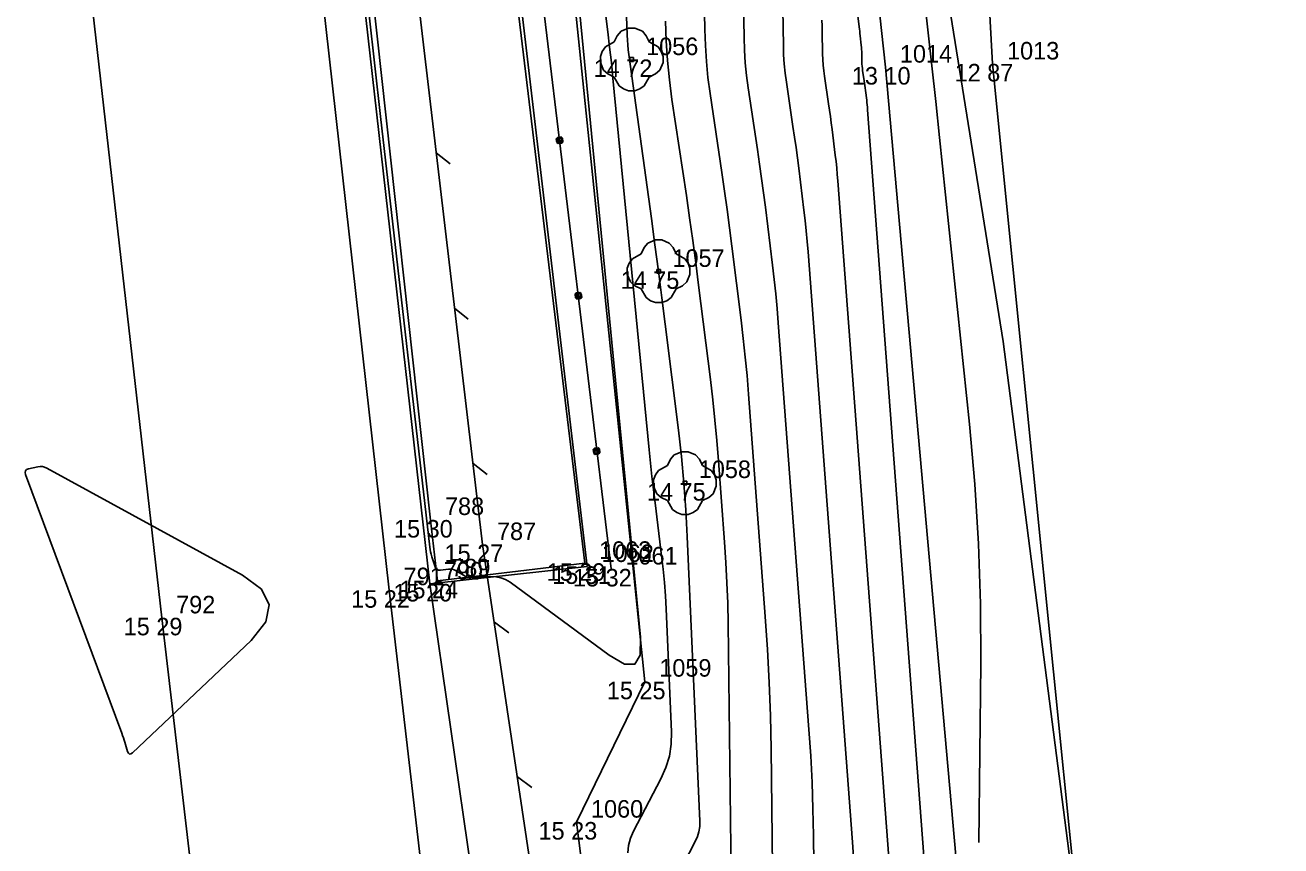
# Model space of a CAD drawing. Extents: x -711234 to -710007, y -1026313 to -1025448.
# Drawn here: x -710920.63 to -710900.59, y -1025784.48 to -1025771.38 of the extents above; entities that cross this region are included whole.
import ezdxf

# ---------------------------------------------------------------- set-up
doc = ezdxf.new("R2010")
doc.units = 0
for name, color, linetype in [('Ex_Major Contours', 7, 'Continuous'), ('Ex_Minor Contours', 7, 'Continuous'), ('Z_body', 7, 'Continuous'), ('Z_body_cisla', 7, 'Continuous'), ('Z_body_vysky_redukovane', 7, 'Continuous'), ('Z_chodnik', 7, 'Continuous'), ('Z_hrany_paty', 7, 'Continuous'), ('Z_katastr_hranice', 7, 'Continuous'), ('Z_komunikace', 7, 'Continuous'), ('Z_obruba', 7, 'Continuous'), ('Z_pole_rozhranni', 7, 'Continuous'), ('Z_svodidla', 7, 'Continuous'), ('Z_svodidla_znacky', 7, 'Continuous'), ('Z_vdz12_plna', 7, 'Continuous'), ('Z_vdz25_plna', 7, 'Continuous'), ('Z_zabradli', 7, 'Continuous'), ('Z_zabradli_znaky', 7, 'Continuous'), ('Z_zelen_jednotliva', 7, 'Continuous')]:
    doc.layers.add(name, color=color, linetype=linetype)

# ---------------------------------------------------------------- blocks, each defined once
blk = doc.blocks.new('POINT_DISPLAY')
blk.add_line((0, 0), (0, 0))
blk = doc.blocks.new('Z24')
for p, q in [((-0.23, 0.38), (-0.17, 0.45)), ((-0.17, 0.45), (-0.05, 0.5)), ((-0.05, 0.5), (0.05, 0.5)), ((0.05, 0.5), (0.17, 0.45)), ((0.17, 0.45), (0.23, 0.38)), ((-0.42, 0.2), (-0.28, 0.28)), ((-0.28, 0.28), (-0.23, 0.38)), ((0.23, 0.38), (0.28, 0.28)), ((0.28, 0.28), (0.42, 0.2)), ((-0.5, 0.05), (-0.47, 0.13)), ((-0.5, -0.05), (-0.5, 0.05)), ((-0.47, 0.13), (-0.42, 0.2)), ((-0.03, -0.03), (-0.03, 0.03)), ((-0.03, 0.03), (0.03, 0.03)), ((0.03, 0.03), (0.03, -0.03)), ((0.42, 0.2), (0.47, 0.13)), ((0.47, 0.13), (0.5, 0.05)), ((0.5, 0.05), (0.5, -0.05)), ((-0.45, -0.17), (-0.5, -0.05)), ((-0.38, -0.23), (-0.45, -0.17)), ((0.03, -0.03), (-0.03, -0.03)), ((0.45, -0.17), (0.38, -0.23)), ((0.5, -0.05), (0.45, -0.17)), ((-0.28, -0.28), (-0.38, -0.23)), ((-0.2, -0.42), (-0.28, -0.28)), ((0.28, -0.28), (0.2, -0.42)), ((0.38, -0.23), (0.28, -0.28)), ((-0.13, -0.47), (-0.2, -0.42)), ((-0.05, -0.5), (-0.13, -0.47)), ((0.05, -0.5), (-0.05, -0.5)), ((0.13, -0.47), (0.05, -0.5)), ((0.2, -0.42), (0.13, -0.47))]:
    blk.add_line(p, q)
blk = doc.blocks.new('Z529')
blk.add_line((0, 0), (0.2, 0.2))
blk = doc.blocks.new('Z530')
for p, q in [((-0.05, 0.03), (-0.03, 0.05)), ((-0.05, -0.03), (-0.05, 0.03)), ((-0.03, 0.05), (0.03, 0.05)), ((-0.03, -0.03), (-0.03, 0.03)), ((-0.03, 0.03), (0.03, 0.03)), ((-0.03, -0.03), (0.03, 0.03)), ((0.03, 0.05), (0.05, 0.03)), ((0.03, 0.03), (0.03, -0.03)), ((0.05, 0.03), (0.05, -0.03)), ((-0.03, -0.05), (-0.05, -0.03)), ((0.03, -0.03), (-0.03, -0.03)), ((0.03, -0.05), (-0.03, -0.05)), ((0.05, -0.03), (0.03, -0.05))]:
    blk.add_line(p, q)

msp = doc.modelspace()

# ---------------------------------------------------------------- linework, layer by layer
at = {"layer": 'Ex_Major Contours'}
for points in [[(-710905.412, -1025784.425), (-710905.38, -1025781.577), (-710905.384, -1025780.619), (-710905.414, -1025779.662), (-710905.473, -1025778.706), (-710905.558, -1025777.751), (-710906.037, -1025773.174), (-710906.098, -1025772.601), (-710906.16, -1025772.029), (-710906.224, -1025771.456), (-710906.29, -1025770.884), (-710906.667, -1025767.642), (-710906.688, -1025767.556), (-710906.729, -1025767.487), (-710906.791, -1025767.436), (-710906.872, -1025767.402), (-710907.239, -1025767.301), (-710907.321, -1025767.267), (-710907.384, -1025767.216), (-710907.428, -1025767.147), (-710907.452, -1025767.062), (-710909.105, -1025756.206)], [(-710909.171, -1025770.773), (-710909.157, -1025771.58), (-710909.15, -1025771.781), (-710909.137, -1025771.982), (-710909.117, -1025772.183), (-710909.09, -1025772.382), (-710908.943, -1025773.369), (-710908.91, -1025773.599), (-710908.877, -1025773.829), (-710908.847, -1025774.059), (-710908.817, -1025774.289), (-710908.703, -1025775.211), (-710908.675, -1025775.442), (-710908.651, -1025775.672), (-710908.629, -1025775.904), (-710908.611, -1025776.135), (-710908.122, -1025782.622), (-710908.094, -1025783.045), (-710908.072, -1025783.468), (-710908.057, -1025783.891), (-710908.049, -1025784.315), (-710908.022, -1025786.591)], [(-710911.01, -1025784.594), (-710910.999, -1025784.474), (-710910.969, -1025784.357), (-710910.92, -1025784.244), (-710910.483, -1025783.411), (-710910.403, -1025783.232), (-710910.349, -1025783.048), (-710910.319, -1025782.858), (-710910.315, -1025782.662), (-710910.401, -1025780.7), (-710910.413, -1025780.488), (-710910.428, -1025780.276), (-710910.448, -1025780.064), (-710910.472, -1025779.853), (-710910.578, -1025779.008), (-710910.603, -1025778.796), (-710910.627, -1025778.585), (-710910.65, -1025778.373), (-710910.671, -1025778.161), (-710911.249, -1025772.228), (-710911.274, -1025771.98), (-710911.302, -1025771.733), (-710911.332, -1025771.487), (-710911.365, -1025771.24)]]:
    msp.add_lwpolyline(points, dxfattribs=at)
at = {"layer": 'Ex_Minor Contours'}
for points in [[(-710915.142, -1025771.224), (-710915.051, -1025772.031), (-710914.959, -1025772.838), (-710914.174, -1025779.712), (-710914.168, -1025779.751), (-710914.161, -1025779.789), (-710914.152, -1025779.827), (-710914.141, -1025779.865), (-710914.088, -1025780.026), (-710914.076, -1025780.053), (-710914.057, -1025780.071), (-710914.033, -1025780.08), (-710914.004, -1025780.08), (-710913.875, -1025780.065), (-710913.843, -1025780.063), (-710913.812, -1025780.067), (-710913.783, -1025780.076), (-710913.754, -1025780.09), (-710913.608, -1025780.177), (-710913.598, -1025780.185), (-710913.595, -1025780.191), (-710913.6, -1025780.196), (-710913.612, -1025780.2), (-710913.676, -1025780.211), (-710913.688, -1025780.214), (-710913.692, -1025780.215), (-710913.688, -1025780.216), (-710913.676, -1025780.215), (-710913.199, -1025780.184), (-710913.116, -1025780.185), (-710913.037, -1025780.201), (-710912.963, -1025780.23), (-710912.892, -1025780.274), (-710911.312, -1025781.438), (-710911.066, -1025781.579), (-710910.9, -1025781.578), (-710910.815, -1025781.436), (-710910.809, -1025781.152), (-710912.067, -1025768.238)], [(-710909.802, -1025770.418), (-710909.784, -1025771.449), (-710909.775, -1025771.707), (-710909.758, -1025771.963), (-710909.733, -1025772.219), (-710909.699, -1025772.475), (-710909.511, -1025773.735), (-710909.468, -1025774.029), (-710909.427, -1025774.323), (-710909.387, -1025774.617), (-710909.35, -1025774.911), (-710909.203, -1025776.089), (-710909.169, -1025776.384), (-710909.137, -1025776.679), (-710909.11, -1025776.974), (-710909.086, -1025777.27), (-710908.819, -1025780.82), (-710908.783, -1025781.348), (-710908.756, -1025781.875), (-710908.737, -1025782.404), (-710908.727, -1025782.932), (-710908.693, -1025785.772)], [(-710908.54, -1025771.128), (-710908.53, -1025771.71), (-710908.525, -1025771.856), (-710908.516, -1025772.001), (-710908.501, -1025772.146), (-710908.482, -1025772.29), (-710908.376, -1025773.002), (-710908.351, -1025773.168), (-710908.328, -1025773.335), (-710908.306, -1025773.501), (-710908.285, -1025773.667), (-710908.202, -1025774.333), (-710908.182, -1025774.499), (-710908.165, -1025774.666), (-710908.149, -1025774.833), (-710908.135, -1025775), (-710907.426, -1025784.423), (-710907.405, -1025784.741)], [(-710911.034, -1025771.236), (-710911.022, -1025771.544), (-710911.018, -1025771.621), (-710911.012, -1025771.697), (-710911.005, -1025771.774), (-710910.995, -1025771.85), (-710910.636, -1025774.466), (-710910.579, -1025774.888), (-710910.523, -1025775.31), (-710910.468, -1025775.733), (-710910.415, -1025776.155), (-710910.205, -1025777.845), (-710910.157, -1025778.268), (-710910.117, -1025778.691), (-710910.086, -1025779.116), (-710910.063, -1025779.541), (-710909.863, -1025784.087), (-710909.865, -1025784.172), (-710909.878, -1025784.254), (-710909.901, -1025784.333), (-710909.936, -1025784.411), (-710910.124, -1025784.77)], [(-710909.364, -1025784.954), (-710909.412, -1025780.934), (-710909.418, -1025780.608), (-710909.43, -1025780.283), (-710909.447, -1025779.958), (-710909.468, -1025779.633), (-710909.566, -1025778.334), (-710909.593, -1025778.009), (-710909.623, -1025777.685), (-710909.657, -1025777.361), (-710909.695, -1025777.037), (-710909.882, -1025775.533), (-710909.928, -1025775.175), (-710909.976, -1025774.817), (-710910.026, -1025774.459), (-710910.078, -1025774.101), (-710910.307, -1025772.567), (-710910.349, -1025772.256), (-710910.38, -1025771.945), (-710910.4, -1025771.632), (-710910.411, -1025771.319)], [(-710906.73, -1025786.225), (-710907.66, -1025773.866), (-710907.669, -1025773.763), (-710907.678, -1025773.66), (-710907.689, -1025773.557), (-710907.701, -1025773.455), (-710907.752, -1025773.045), (-710907.765, -1025772.943), (-710907.779, -1025772.84), (-710907.793, -1025772.738), (-710907.808, -1025772.636), (-710907.874, -1025772.198), (-710907.885, -1025772.109), (-710907.894, -1025772.02), (-710907.9, -1025771.931), (-710907.903, -1025771.841), (-710907.91, -1025771.482), (-710907.912, -1025771.393), (-710907.917, -1025771.303)], [(-710907.34, -1025771.235), (-710907.32, -1025771.408), (-710907.316, -1025771.444), (-710907.312, -1025771.48), (-710907.307, -1025771.516), (-710907.304, -1025771.552), (-710907.287, -1025771.703), (-710907.284, -1025771.737), (-710907.281, -1025771.77), (-710907.28, -1025771.804), (-710907.279, -1025771.837), (-710907.276, -1025771.972), (-710907.275, -1025772.005), (-710907.273, -1025772.039), (-710907.269, -1025772.072), (-710907.265, -1025772.105), (-710907.241, -1025772.27), (-710907.235, -1025772.308), (-710907.23, -1025772.346), (-710907.224, -1025772.385), (-710907.22, -1025772.423), (-710907.2, -1025772.577), (-710907.196, -1025772.615), (-710907.192, -1025772.654), (-710907.188, -1025772.692), (-710907.185, -1025772.731), (-710906.034, -1025788.026)]]:
    msp.add_lwpolyline(points, dxfattribs=at)
msp.add_lwpolyline([(-710920.606, -1025778.475), (-710920.625, -1025778.494), (-710920.63, -1025778.519), (-710920.623, -1025778.552), (-710919.087, -1025782.683), (-710919.074, -1025782.719), (-710919.062, -1025782.755), (-710919.05, -1025782.791), (-710919.039, -1025782.827), (-710918.994, -1025782.973), (-710918.981, -1025783.002), (-710918.964, -1025783.015), (-710918.942, -1025783.012), (-710918.917, -1025782.994), (-710917.025, -1025781.203), (-710916.79, -1025780.907), (-710916.734, -1025780.635), (-710916.857, -1025780.386), (-710917.16, -1025780.16), (-710920.285, -1025778.45), (-710920.319, -1025778.435), (-710920.354, -1025778.427), (-710920.39, -1025778.425), (-710920.427, -1025778.43), (-710920.576, -1025778.463)], close=True, dxfattribs=at)
at = {"layer": 'Z_chodnik'}
for p in [(-710913.27, -1025766.93), (-710914.05, -1025780.25)]:
    msp.add_line(p, (-710911.7, -1025779.97), dxfattribs=at)
at = {"layer": 'Z_hrany_paty'}
for p, q in [((-710906.9, -1025772.05), (-710908.73, -1025755.25)), ((-710912.23, -1025767.44), (-710910.74, -1025781.86)), ((-710905.31, -1025789.9), (-710906.9, -1025772.05)), ((-710910.74, -1025781.86), (-710911.83, -1025784.1)), ((-710911.83, -1025784.1), (-710910.44, -1025795.35))]:
    msp.add_line(p, q, dxfattribs=at)
at = {"layer": 'Z_katastr_hranice'}
msp.add_lwpolyline([(-710889, -1025970.31), (-710889.68, -1025960.38), (-710892.53, -1025890.03), (-710898.37, -1025828.05), (-710905.02, -1025776.43), (-710911.59, -1025735.63)], dxfattribs=at)
at = {"layer": 'Z_komunikace'}
for p, q in [((-710915.93, -1025764.78), (-710914.17, -1025780.3)), ((-710914.17, -1025780.3), (-710912.02, -1025795.18))]:
    msp.add_line(p, q, dxfattribs=at)
at = {"layer": 'Z_obruba'}
for p, q in [((-710915.76, -1025764.75), (-710914.16, -1025779.28)), ((-710913.2, -1025766.93), (-710911.66, -1025780.02)), ((-710914.16, -1025779.28), (-710914.05, -1025780.25)), ((-710911.66, -1025780.02), (-710914.17, -1025780.3))]:
    msp.add_line(p, q, dxfattribs=at)
at = {"layer": 'Z_pole_rozhranni'}
for p, q in [((-710905.19, -1025772), (-710906.14, -1025755.5)), ((-710903.51, -1025788.79), (-710905.19, -1025772))]:
    msp.add_line(p, q, dxfattribs=at)
at = {"layer": 'Z_svodidla'}
for p, q in [((-710915.1, -1025764.73), (-710913.33, -1025779.67)), ((-710913.33, -1025779.67), (-710911.02, -1025795.09))]:
    msp.add_line(p, q, dxfattribs=at)
at = {"layer": 'Z_vdz12_plna'}
for p, q in [((-710920.24, -1025765.07), (-710918.45, -1025780.84)), ((-710918.45, -1025780.84), (-710916.74, -1025795.45))]:
    msp.add_line(p, q, dxfattribs=at)
at = {"layer": 'Z_vdz25_plna'}
for p, q in [((-710916.55, -1025765.02), (-710914.82, -1025780.4)), ((-710914.82, -1025780.4), (-710913.1, -1025795.25))]:
    msp.add_line(p, q, dxfattribs=at)
at = {"layer": 'Z_zabradli'}
msp.add_line((-710912.85, -1025767.01), (-710911.28, -1025780.06), dxfattribs=at)

# ---------------------------------------------------------------- block references
at = {"layer": 'Z_body'}
for p in [(-710910.95, -1025771.93), (-710906.9, -1025772.05), (-710905.19, -1025772), (-710910.52, -1025775.31), (-710910.1, -1025778.69), (-710914.16, -1025779.28), (-710913.33, -1025779.67), (-710911.7, -1025779.97), (-710911.66, -1025780.02), (-710911.28, -1025780.06), (-710914.82, -1025780.4), (-710914.17, -1025780.3), (-710914.05, -1025780.25), (-710918.45, -1025780.84), (-710910.74, -1025781.86), (-710911.83, -1025784.1)]:
    msp.add_blockref('POINT_DISPLAY', p, dxfattribs=at)
at = {"layer": 'Z_svodidla_znacky'}
for p, rotation in [((-710914.07, -1025773.42), -83.19999999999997), ((-710913.78, -1025775.9), -83.19999999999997), ((-710913.48, -1025778.38), -83.19999999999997), ((-710913.14, -1025780.91), -81.50000000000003), ((-710912.77, -1025783.38), -81.50000000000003)]:
    msp.add_blockref('Z529', p, dxfattribs=dict(at, rotation=rotation))
at = {"layer": 'Z_zabradli_znaky', "rotation": -83.10000000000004}
for p in [(-710912.1, -1025773.22), (-710911.8, -1025775.7), (-710911.51, -1025778.18)]:
    msp.add_blockref('Z530', p, dxfattribs=at)
at = {"layer": 'Z_zelen_jednotliva'}
for p in [(-710910.95, -1025771.93), (-710910.52, -1025775.31), (-710910.1, -1025778.69)]:
    msp.add_blockref('Z24', p, dxfattribs=at)

# ---------------------------------------------------------------- texts
at = {"layer": 'Z_body_cisla'}
for s, p in [('1056', (-710910.72, -1025771.86)), ('1014', (-710906.67, -1025771.98)), ('1013', (-710904.96, -1025771.93)), ('1057', (-710910.3, -1025775.24)), ('1058', (-710909.88, -1025778.61)), ('788', (-710913.93, -1025779.2)), ('787', (-710913.1, -1025779.6)), ('1063', (-710911.47, -1025779.9)), ('1062', (-710911.43, -1025779.95)), ('1061', (-710911.05, -1025779.99)), ('790', (-710913.95, -1025780.23)), ('789', (-710913.83, -1025780.18)), ('791', (-710914.59, -1025780.32)), ('792', (-710918.22, -1025780.77)), ('1059', (-710910.51, -1025781.78)), ('1060', (-710911.6, -1025784.03))]:
    msp.add_text(s, height=0.28, dxfattribs=at).set_placement(p)
at = {"layer": 'Z_body_vysky_redukovane'}
for s, p in [('14 72', (-710911.557, -1025772.21)), ('13 10', (-710907.437, -1025772.33)), ('12 87', (-710905.797, -1025772.28)), ('14 75', (-710911.127, -1025775.59)), ('14 75', (-710910.707, -1025778.97)), ('15 30', (-710914.743, -1025779.56)), ('15 27', (-710913.937, -1025779.95)), ('15 29', (-710912.307, -1025780.25)), ('15 31', (-710912.22, -1025780.3)), ('15 32', (-710911.887, -1025780.34)), ('15 22', (-710915.427, -1025780.68)), ('15 20', (-710914.753, -1025780.58)), ('15 24', (-710914.657, -1025780.53)), ('15 29', (-710919.057, -1025781.12)), ('15 25', (-710911.347, -1025782.14)), ('15 23', (-710912.437, -1025784.38))]:
    msp.add_text(s, height=0.28, dxfattribs=at).set_placement(p)

doc.saveas('drawing.dxf')
